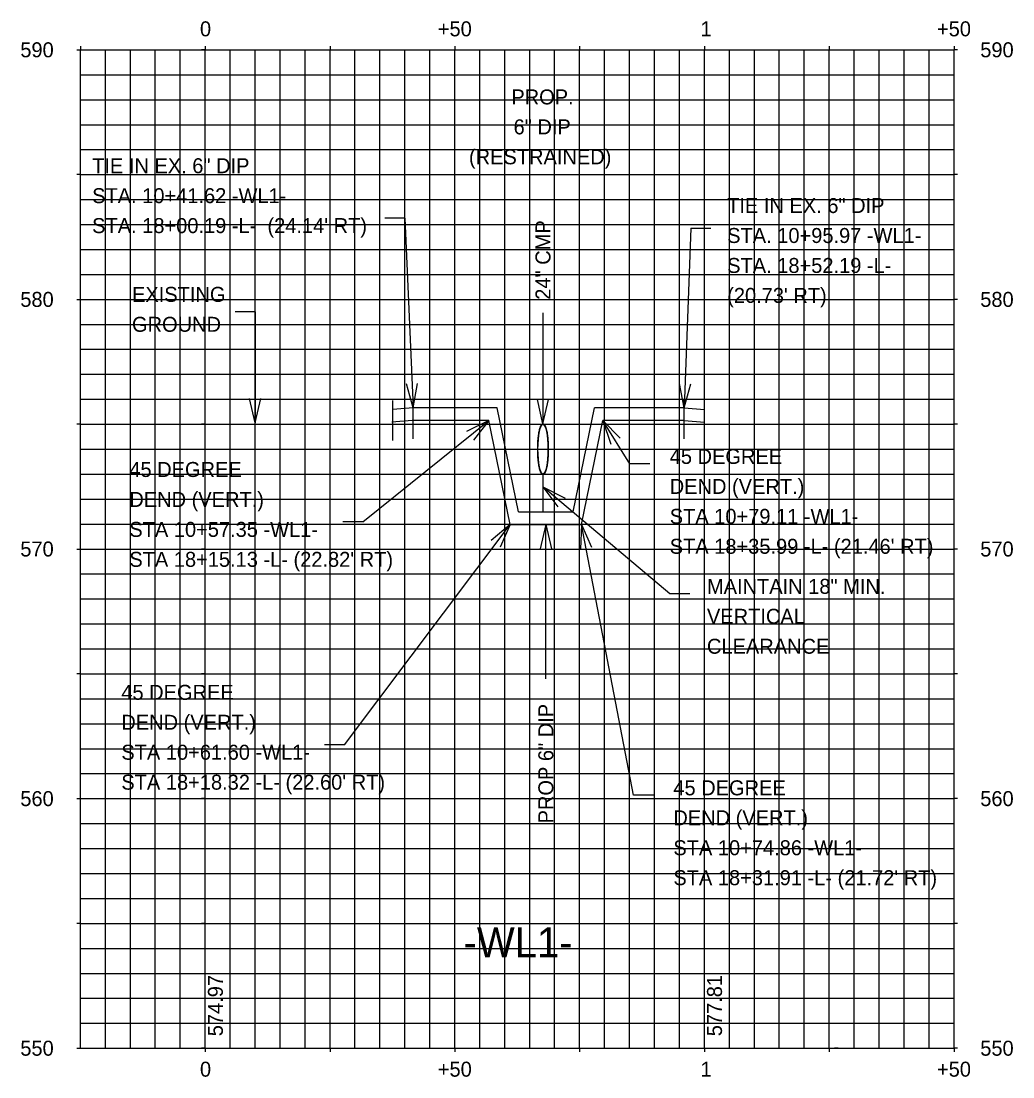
# Model space of a CAD drawing. Extents: x -37 to 162, y 544 to 756.
import ezdxf

# ---------------------------------------------------------------- set-up
doc = ezdxf.new("R2010")
doc.units = 0
for name, color, linetype in [('Default', 7, 'Continuous'), ('Exist Utilities Water Text', 7, 'Continuous'), ('P_NCDOT_Horizontal_Alignment', 7, 'Continuous'), ('P_RDY_Easement_Construction_Station_Offsets', 7, 'Continuous'), ('P_UTL_Water_Service_Line', 7, 'Continuous'), ('P_UTL_Water_Text', 7, 'Continuous'), ('Scratch_Level_0', 7, 'Continuous'), ('Scratch_Level_1', 7, 'Continuous'), ('Scratch_Level_3', 7, 'Continuous')]:
    doc.layers.add(name, color=color, linetype=linetype)

msp = doc.modelspace()

# ---------------------------------------------------------------- linework, layer by layer
at = {"layer": 'Default'}
for p, q in [((40, 716.28), (36, 716.28)), ((40, 716.28), (41.62, 678.25)), ((97.31, 714.3), (95.97, 678.25)), ((97.31, 714.3), (101.31, 714.3)), ((10, 697.53), (6, 697.53)), ((10, 697.53), (10, 675.25)), ((67.66, 697.34), (67.66, 675.06)), ((41.62, 678.25), (42.54, 683.17)), ((95.97, 678.25), (95.03, 683.16)), ((41.62, 678.25), (40.29, 683.07)), ((95.97, 678.25), (97.27, 683.08)), ((10, 675.25), (8.88, 680.12)), ((10, 675.25), (11.12, 680.12)), ((37.59, 671.72), (37.59, 679.72)), ((41.62, 672.04), (41.62, 680.04)), ((67.66, 675.06), (66.54, 679.94)), ((67.66, 675.06), (68.78, 679.94)), ((95.97, 672.04), (95.97, 680.04)), ((100, 671.72), (100, 679.72)), ((41.62, 678.25), (37.59, 677.93)), ((58.48, 678.25), (41.62, 678.25)), ((62.73, 657.44), (58.48, 678.25)), ((73.72, 657.44), (77.97, 678.25)), ((95.97, 678.25), (77.97, 678.25)), ((95.97, 678.25), (100, 677.93)), ((31.59, 655.43), (56.84, 675.75)), ((41.43, 675.74), (37.4, 675.42)), ((56.84, 675.75), (41.62, 675.75)), ((56.84, 675.75), (52.34, 673.57)), ((56.84, 675.75), (53.75, 671.82)), ((61.09, 654.94), (56.84, 675.75)), ((75.37, 654.94), (79.62, 675.75)), ((85.05, 667.04), (79.62, 675.75)), ((79.62, 675.75), (81.24, 671.02)), ((79.62, 675.75), (83.15, 672.21)), ((95.97, 675.75), (79.62, 675.75)), ((95.97, 675.75), (100, 675.43)), ((89.05, 667.04), (85.05, 667.04)), ((67.66, 664.94), (67.66, 657.44)), ((93.08, 641.02), (67.66, 662.46)), ((67.66, 662.46), (72.11, 660.18)), ((67.66, 662.46), (70.66, 658.46)), ((62.73, 657.44), (73.72, 657.44)), ((31.59, 655.43), (27.59, 655.43)), ((27.9, 610.79), (61.09, 654.94)), ((61.09, 654.94), (57.26, 651.72)), ((61.09, 654.94), (59.06, 650.37)), ((61.09, 654.94), (75.37, 654.94)), ((68.23, 654.94), (67.1, 650.06)), ((68.23, 624), (68.23, 654.94)), ((68.23, 654.94), (69.35, 650.06)), ((75.37, 654.94), (75.18, 649.94)), ((85.78, 600.66), (75.37, 654.94)), ((75.37, 654.94), (77.39, 650.36)), ((97.08, 641.02), (93.08, 641.02)), ((27.9, 610.79), (23.9, 610.79)), ((89.78, 600.66), (85.78, 600.66))]:
    msp.add_line(p, q, dxfattribs=at)
msp.add_ellipse((67.66, 670), major_axis=(0, -5), ratio=0.2, dxfattribs=at)
msp.add_open_spline([(67.66, 664.94), (67.68, 664.94), (67.7, 664.94), (67.75, 664.95), (67.77, 664.96), (67.81, 664.98), (67.83, 664.99), (67.86, 665.02), (67.88, 665.03), (67.92, 665.07), (67.94, 665.09), (67.97, 665.13), (67.99, 665.16), (68.04, 665.23), (68.07, 665.29), (68.13, 665.42), (68.16, 665.49), (68.22, 665.64), (68.25, 665.73), (68.33, 666.01), (68.38, 666.22), (68.48, 666.69), (68.52, 666.94), (68.59, 667.49), (68.62, 667.78), (68.7, 668.68), (68.72, 669.34), (68.72, 670.66), (68.7, 671.32), (68.62, 672.22), (68.59, 672.51), (68.52, 673.06), (68.48, 673.31), (68.38, 673.78), (68.33, 673.99), (68.25, 674.27), (68.22, 674.36), (68.16, 674.51), (68.13, 674.58), (68.07, 674.71), (68.04, 674.77), (67.99, 674.84), (67.97, 674.87), (67.94, 674.91), (67.92, 674.93), (67.88, 674.97), (67.86, 674.98), (67.83, 675.01), (67.81, 675.02), (67.77, 675.04), (67.75, 675.05), (67.7, 675.06), (67.68, 675.06), (67.64, 675.06), (67.62, 675.06), (67.57, 675.05), (67.55, 675.04), (67.51, 675.02), (67.49, 675.01), (67.46, 674.98), (67.44, 674.97), (67.4, 674.93), (67.38, 674.91), (67.35, 674.87), (67.33, 674.84), (67.28, 674.77), (67.25, 674.71), (67.19, 674.58), (67.16, 674.51), (67.1, 674.36), (67.07, 674.27), (66.99, 673.99), (66.94, 673.78), (66.84, 673.31), (66.8, 673.06), (66.73, 672.51), (66.7, 672.22), (66.62, 671.32), (66.6, 670.66), (66.6, 669.34), (66.62, 668.68), (66.7, 667.78), (66.73, 667.49), (66.8, 666.94), (66.84, 666.69), (66.94, 666.22), (66.99, 666.01), (67.07, 665.73), (67.1, 665.64), (67.16, 665.49), (67.19, 665.42), (67.25, 665.29), (67.28, 665.23), (67.33, 665.16), (67.35, 665.13), (67.38, 665.09), (67.4, 665.07), (67.44, 665.03), (67.46, 665.02), (67.49, 664.99), (67.51, 664.98), (67.55, 664.96), (67.57, 664.95), (67.62, 664.94), (67.64, 664.94), (67.66, 664.94)], degree=3, dxfattribs=at)
at = {"layer": 'P_RDY_Easement_Construction_Station_Offsets'}
for p, q in [((-25, 550), (-25, 750)), ((-20, 550), (-20, 750)), ((-15, 550), (-15, 750)), ((-10, 550), (-10, 750)), ((-5, 550), (-5, 750)), ((0, 550), (0, 750)), ((5, 550), (5, 750)), ((10, 550), (10, 750)), ((15, 550), (15, 750)), ((20, 550), (20, 750)), ((30, 550), (30, 750)), ((35, 550), (35, 750)), ((40, 550), (40, 750)), ((45, 550), (45, 750)), ((55, 550), (55, 750)), ((60, 550), (60, 750)), ((65, 550), (65, 750)), ((70, 550), (70, 750)), ((80, 550), (80, 750)), ((85, 550), (85, 750)), ((90, 550), (90, 750)), ((95, 550), (95, 750)), ((105, 550), (105, 750)), ((110, 550), (110, 750)), ((115, 550), (115, 750)), ((120, 550), (120, 750)), ((130, 550), (130, 750)), ((135, 550), (135, 750)), ((140, 550), (140, 750)), ((145, 550), (145, 750)), ((-25, 745), (150, 745)), ((-25, 740), (150, 740)), ((-25, 735), (150, 735)), ((-25, 730), (150, 730)), ((-25, 720), (150, 720)), ((-25, 715), (150, 715)), ((-25, 710), (150, 710)), ((-25, 705), (150, 705)), ((-25, 695), (150, 695)), ((-25, 690), (150, 690)), ((-25, 685), (150, 685)), ((-25, 680), (150, 680)), ((-25, 670), (150, 670)), ((-25, 665), (150, 665)), ((-25, 660), (150, 660)), ((-25, 655), (150, 655)), ((-25, 645), (150, 645)), ((-25, 640), (150, 640)), ((-25, 635), (150, 635)), ((-25, 630), (150, 630)), ((-25, 620), (150, 620)), ((-25, 615), (150, 615)), ((-25, 610), (150, 610)), ((-25, 605), (150, 605)), ((-25, 595), (150, 595)), ((-25, 590), (150, 590)), ((-25, 585), (150, 585)), ((-25, 580), (150, 580)), ((-25, 570), (150, 570)), ((-25, 565), (150, 565)), ((-25, 560), (150, 560)), ((-25, 555), (150, 555))]:
    msp.add_line(p, q, dxfattribs=at)
at = {"layer": 'P_UTL_Water_Service_Line'}
for p, q in [((-25, 750), (150, 750)), ((-25, 550), (-25, 750)), ((150, 550), (150, 750)), ((-25, 550), (150, 550))]:
    msp.add_line(p, q, dxfattribs=at)
at = {"layer": 'P_UTL_Water_Text'}
for p, q in [((50, 550), (50, 750)), ((100, 550), (100, 750)), ((-25, 700), (150, 700)), ((-25, 650), (150, 650)), ((-25, 600), (150, 600))]:
    msp.add_line(p, q, dxfattribs=at)
at = {"layer": 'Scratch_Level_0'}
for p, q in [((-25.72, 750), (-25, 750)), ((-25, 750.72), (-25, 750)), ((-25, 550), (-25, 750)), ((0, 750), (-0.72, 750)), ((0, 750.72), (0, 750)), ((0, 550), (0, 750)), ((25, 750.72), (25, 750)), ((25, 550), (25, 750)), ((50, 750.72), (50, 750)), ((50, 550), (50, 750)), ((75, 750.72), (75, 750)), ((75, 550), (75, 750)), ((100, 750.72), (100, 750)), ((100, 550), (100, 750)), ((125, 750.72), (125, 750)), ((125, 550), (125, 750)), ((125, 550), (125, 750)), ((150, 750.72), (150, 750)), ((150, 750.72), (150, 750)), ((150.72, 750), (150, 750)), ((150, 550), (150, 750)), ((150, 550), (150, 750)), ((150, 550), (150, 750)), ((150, 550), (150, 750)), ((150, 550), (150, 750)), ((150, 550), (150, 750)), ((150, 550), (150, 750)), ((-25, 725), (-25.72, 725)), ((-25, 725), (150, 725)), ((0, 725), (-0.72, 725)), ((150.72, 725), (150, 725)), ((-25.72, 700), (-25, 700)), ((0, 700), (-0.72, 700)), ((0, 700), (126.06, 700)), ((150.72, 700), (150, 700)), ((-25, 675), (-25.72, 675)), ((-25, 675), (150, 675)), ((0, 675), (-0.72, 675)), ((150.72, 675), (150, 675)), ((-25.72, 650), (-25, 650)), ((0, 650), (-0.72, 650)), ((150.72, 650), (150, 650)), ((-25, 625), (-25.72, 625)), ((-25, 625), (150, 625)), ((0, 625), (-0.72, 625)), ((150.72, 625), (150, 625)), ((-25.72, 600), (-25, 600)), ((0, 600), (-0.72, 600)), ((150.72, 600), (150, 600)), ((-25, 575), (-25.72, 575)), ((-25, 575), (150, 575)), ((0, 575), (-0.72, 575)), ((150.72, 575), (150, 575)), ((-25.72, 550), (-25, 550)), ((0, 550), (-0.72, 550)), ((0, 550), (0, 549.28)), ((25, 550), (25, 549.28)), ((50, 550), (50, 549.28)), ((75, 550), (75, 549.28)), ((100, 550), (100, 549.28)), ((125, 550), (125, 549.28)), ((126.78, 550), (126.06, 550)), ((150.72, 550), (150, 550)), ((150, 550), (150, 549.28)), ((150, 550), (150, 549.28))]:
    msp.add_line(p, q, dxfattribs=at)

# ---------------------------------------------------------------- texts
at = {"layer": 'Default'}
for s, p in [('PROP.', (61.32, 739.06)), ('6" DIP', (61.77, 733.06)), ('(RESTRAINED)', (52.83, 727.06)), ('TIE IN EX. 6" DIP', (-22.66, 725.28)), ('STA. 10+41.62 -WL1-', (-22.66, 719.28)), ('TIE IN EX. 6" DIP', (104.56, 717.3)), ("STA. 18+00.19 -L-  (24.14' RT)", (-22.66, 713.28)), ('STA. 10+95.97 -WL1-', (104.56, 711.3)), ('STA. 18+52.19 -L-  ', (104.56, 705.3)), ('EXISTING', (-14.67, 699.51)), ("(20.73' RT)", (104.56, 699.3)), ('GROUND', (-14.67, 693.51)), ('45 DEGREE', (93.05, 667.04)), ('45 DEGREE', (-15.21, 664.43)), ('DEND (VERT.)', (93.05, 661.04)), ('DEND (VERT.)', (-15.21, 658.43)), ('STA 10+79.11 -WL1-', (93.05, 655.04)), ('STA 10+57.35 -WL1-', (-15.21, 652.43)), ("STA 18+35.99 -L- (21.46' RT)", (93.05, 649.04)), ("STA 18+15.13 -L- (22.82' RT)", (-15.21, 646.43)), ('MAINTAIN 18" MIN.', (100.51, 641.02)), ('VERTICAL ', (100.51, 635.02)), ('CLEARANCE', (100.51, 629.02)), ('45 DEGREE', (-16.81, 619.79)), ('DEND (VERT.)', (-16.81, 613.79)), ('STA 10+61.60 -WL1-', (-16.81, 607.79)), ("STA 18+18.32 -L- (22.60' RT)", (-16.81, 601.79)), ('45 DEGREE', (93.78, 600.66)), ('DEND (VERT.)', (93.78, 594.66)), ('STA 10+74.86 -WL1-', (93.78, 588.66)), ("STA 18+31.91 -L- (21.72' RT)", (93.78, 582.66))]:
    msp.add_text(s, height=3, dxfattribs=at).set_placement(p)
for s, p in [('24" CMP', (69.16, 699.93)), ('PROP 6" DIP', (69.73, 595.03))]:
    msp.add_text(s, height=3, rotation=90, dxfattribs=at).set_placement(p)
at = {"layer": 'Exist Utilities Water Text'}
for s, p in [('590', (-37.05, 748.5)), ('590', (155.26, 748.5)), ('580', (-37.05, 698.5)), ('580', (155.26, 698.5)), ('570', (-37.05, 648.5)), ('570', (155.26, 648.5)), ('560', (-37.05, 598.5)), ('560', (155.26, 598.5)), ('550', (-37.05, 548.5)), ('550', (155.26, 548.5))]:
    msp.add_text(s, height=3, dxfattribs=at).set_placement(p)
at = {"layer": 'P_NCDOT_Horizontal_Alignment'}
for s, p in [('574.97', (3.53, 552.4)), ('577.81', (103.52, 552.4))]:
    msp.add_text(s, height=3, rotation=90, dxfattribs=at).set_placement(p)
at = {"layer": 'Scratch_Level_1'}
msp.add_text('-WL1-', height=6, dxfattribs=at).set_placement((51.75, 568.21))
at = {"layer": 'Scratch_Level_3'}
for s, p in [('0', (-1.06, 752.7)), ('+50', (46.59, 752.7)), ('1', (99.22, 752.7)), ('+50', (146.59, 752.7)), ('0', (-1.06, 544.3)), ('+50', (46.59, 544.3)), ('1', (99.22, 544.3)), ('+50', (146.59, 544.3))]:
    msp.add_text(s, height=3, dxfattribs=at).set_placement(p)

doc.saveas('drawing.dxf')
